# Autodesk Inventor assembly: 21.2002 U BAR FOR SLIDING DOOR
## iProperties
Created: 2007-05
Part Number: 21.2002 U BAR FOR SLIDING DOOR
Document SubType Name: Assembly
Designer: Andy Moles
Mass: 139.857 g
Surface Area: 84.5789 cm^2
Volume: 17.8142 cm^3
Density: 7.85088 g/cm^3
Author: Andy Moles
